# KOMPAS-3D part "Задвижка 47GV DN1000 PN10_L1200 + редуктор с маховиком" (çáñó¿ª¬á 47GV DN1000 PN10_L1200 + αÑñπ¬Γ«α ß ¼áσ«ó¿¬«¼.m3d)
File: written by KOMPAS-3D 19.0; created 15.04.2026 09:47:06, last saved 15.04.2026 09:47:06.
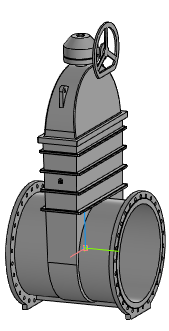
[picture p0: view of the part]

Document properties: Автор: Энергия; Полное имя файла: ..\..\Задвижка 47GV DN1000 PN10_L1200 + редуктор с маховиком.a3d

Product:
- Part/product: Задвижка 47GV DN1000 PN10_L1200 + редуктор с маховиком
    Масса: 5519.4

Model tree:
1. Операция без истории:1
